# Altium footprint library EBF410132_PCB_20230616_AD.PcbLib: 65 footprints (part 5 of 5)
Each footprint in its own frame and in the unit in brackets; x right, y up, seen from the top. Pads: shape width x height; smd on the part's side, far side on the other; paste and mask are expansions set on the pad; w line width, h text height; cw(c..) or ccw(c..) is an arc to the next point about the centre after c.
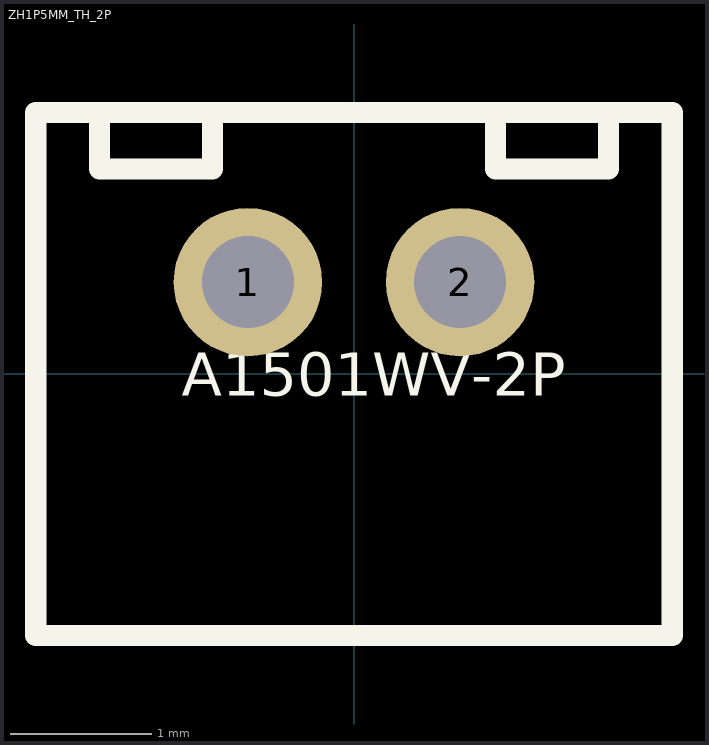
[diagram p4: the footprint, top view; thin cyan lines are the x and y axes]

## ZH1P5MM_TH_2P [mm] "ZH1P5MM_TH_2P"
pads (2):
  round 1.05 hole 0.65: 1(-0.75,0.65) 2(0.75,0.65)
Top Overlay:
  lines w0.15: -1.8,1.85 -1.8,1.45 -1,1.45 -1,1.85 ; 1,1.85 1,1.45 1.8,1.45 1.8,1.85 ; -2.25,-1.85 2.25,-1.85 2.25,1.85 -2.25,1.85 -2.25,-1.85
  text "A1501WV-2P" at -1.219,-0.152 h0.3
Top 3D Body:
  lines w0.025: -2.2,-1.85 2.2,-1.85 2.2,1.85 -2.2,1.85 -2.2,-1.85
Mechanical 15:
  text "1" at -1.065,0.65 h0.79
  text "2" at 0.435,0.65 h0.79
